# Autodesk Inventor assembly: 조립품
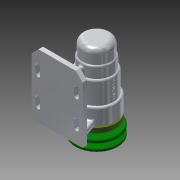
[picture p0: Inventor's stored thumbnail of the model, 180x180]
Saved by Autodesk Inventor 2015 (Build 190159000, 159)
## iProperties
Created: 2017-09
Part Number: 조립품
Document SubType Name: Assembly
Designer: Administrator
Author: Administrator
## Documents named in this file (12)
- C:\Users\Administrator\Desktop\470908V1010\조립품.iam
- C:\Users\Administrator\Desktop\470908V1010\V벨트풀리.ipt
- C:\Users\Administrator\Desktop\470908V1010\멈춤나사 M3x8.ipt
- C:\Users\Administrator\Desktop\470908V1010\베어링 6004.ipt
- C:\Users\Administrator\Desktop\470908V1010\베어링 51202.ipt
- C:\Users\Administrator\Desktop\470908V1010\본체.ipt
- C:\Users\Administrator\Desktop\470908V1010\볼트 M4 x 12.ipt
- C:\Users\Administrator\Desktop\470908V1010\어댑터슬리브.ipt
- C:\Users\Administrator\Desktop\470908V1010\오일 실 20x35x7.ipt
- C:\Users\Administrator\Desktop\470908V1010\축.ipt
- C:\Users\Administrator\Desktop\470908V1010\커버.ipt
- C:\Users\Administrator\Desktop\470908V1010\키 5 x 5 x 16.ipt
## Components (1 placed, 1 different names)
1. V벨트풀리:1 — 각도:2
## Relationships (1: Angle 1)
- 각도:2 [Angle]: V벨트풀리:1
